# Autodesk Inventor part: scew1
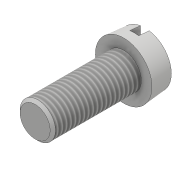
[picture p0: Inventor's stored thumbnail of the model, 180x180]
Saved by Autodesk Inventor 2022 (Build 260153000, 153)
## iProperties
Created: 2016-05
Part Number: scew1
Material: Generic
Document SubType Name: Modeling
Designer: CADCIM
Density: 1 g/cm^3
Appearance: Default
Author: CADCIM
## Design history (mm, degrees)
sketch "Sketch1"
  geometry: C1 r 9.6 at (0, 0); 1 further point
  constraints: 1 centre point, 1 coincident
  dimensions: "d0" = 19.2 diameter of C1
extrude "Extrusion1" new body sketch "Sketch1" distance "d1" = 7.2; taper "d2" = -5 deg
sketch "Sketch3"
  geometry: C1 r 6 at (0, 0); 1 further point
  constraints: 1 centre point, 1 coincident
  dimensions: "d7" = 12 diameter of C1
extrude "Extrusion3" join sketch "Sketch3" distance "d8" = 30; taper "d9" = 0 deg
thread "Thread1" dims "d13" = 10, "d14" = 0
chamfer "Chamfer2" distance "d15" = 0.9; stored, may be unused: second distance "d16" = 2, angle "d17" = 45 deg
sketch "Sketch4"
  geometry: L1 (1.5, -10.35)-(-1.5, -10.35); L2 (-1.5, -10.35)-(-1.5, 10.35); L3 (-1.5, 10.35)-(1.5, 10.35); L4 (1.5, 10.35)-(1.5, -10.35); L5 (0, -10.35)-(0, 10.35); 2 further points
  constraints: 10 end point, 3 midpoint, 2 parallel, 1 coincident, 1 horizontal, 1 perpendicular
  dimensions: "d18" = 3 distance of L1.start L1.end
extrude "Extrusion4" cut sketch "Sketch4" distance "d19" = 3.6; taper "d20" = 0 deg
body "Solid1"
